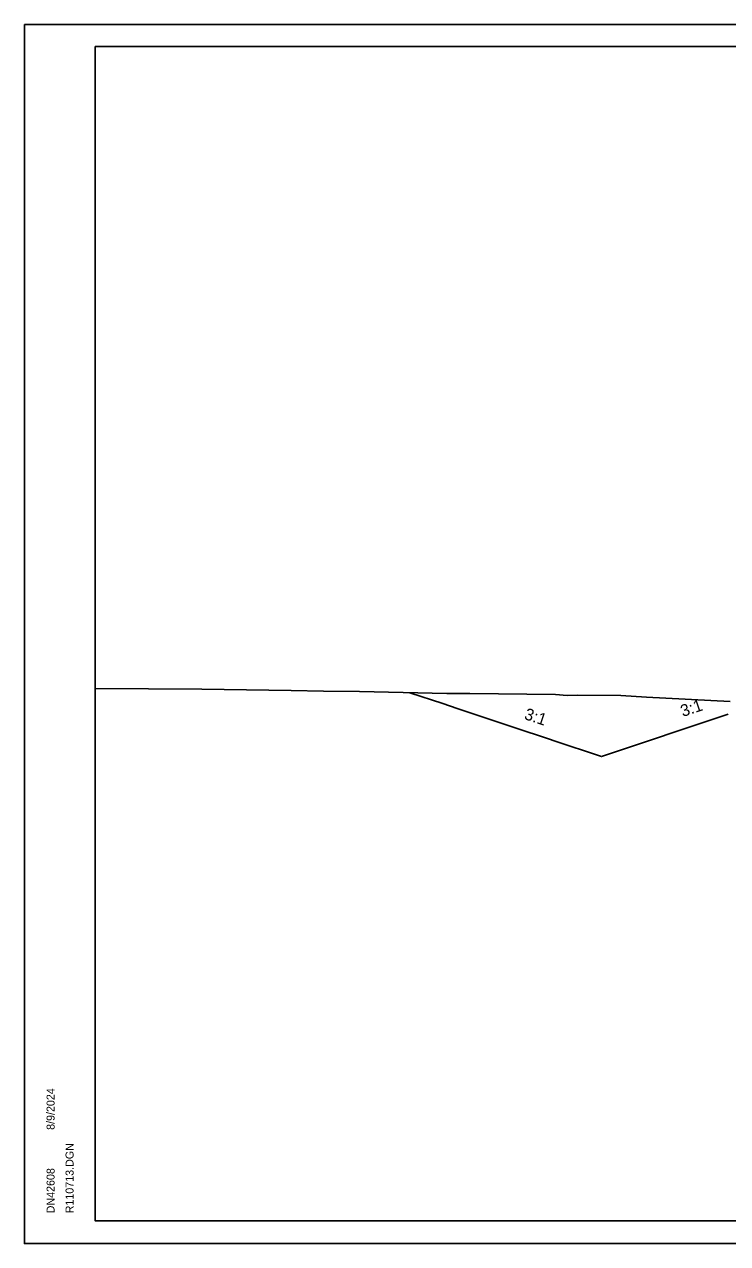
# Model space of a CAD drawing. Extents: x 1678017 to 1687792, y 404433 to 413488.
# Drawn here: x 1679716 to 1680331, y 406203 to 407270 of the extents above; entities that cross this region are included whole.
import ezdxf

# ---------------------------------------------------------------- set-up
doc = ezdxf.new("R2010")
doc.units = 0
for name, color, linetype in [('S_BUILDING', 7, 'Continuous'), ('S_ELECTRIC_UTILITIES', 7, 'Continuous'), ('S_MISC_STRUCTURES_ANNOT', 7, 'Continuous'), ('S_SECONDARY_CTL', 7, 'Continuous'), ('S_STREAM', 7, 'Continuous')]:
    doc.layers.add(name, color=color, linetype=linetype)

msp = doc.modelspace()

# ---------------------------------------------------------------- linework, layer by layer
at = {"layer": 'S_BUILDING'}
for p, q in [((1679778, 407250.2), (1681358.9, 407250.2)), ((1679778, 406222.9), (1679778, 407250.2)), ((1679778, 406222.9), (1679778, 406222.9)), ((1681358.9, 406222.9), (1679778, 406222.9))]:
    msp.add_line(p, q, dxfattribs=at)
at = {"layer": 'S_ELECTRIC_UTILITIES'}
msp.add_lwpolyline([(1680053.1, 406684.9), (1680081.9, 406675.4), (1680094.4, 406671.2), (1680129.5, 406659.5), (1680136.4, 406657.2), (1680139.9, 406656), (1680143.5, 406654.8), (1680176, 406644), (1680178.4, 406643.2), (1680220.6, 406629.1), (1680331.3, 406666.3)], dxfattribs=at)
at = {"layer": 'S_SECONDARY_CTL'}
msp.add_lwpolyline([(1679778, 406688.8), (1679871.1, 406688), (1679949.3, 406686.8), (1679977.5, 406686.3), (1680008.9, 406685.9), (1680085.4, 406684.2), (1680105.5, 406684.2), (1680180.4, 406683.3), (1680190.6, 406682.4), (1680199.6, 406682.9), (1680237.7, 406682.5), (1680260.1, 406681), (1680333.2, 406677.3)], dxfattribs=at)
at = {"layer": 'S_STREAM'}
for p, q in [((1679716, 407269.7), (1681382.7, 407269.7)), ((1679716, 406203), (1681382.7, 406203))]:
    msp.add_line(p, q, dxfattribs=at)
for points in [[(1679716, 407269.7), (1681382.7, 407269.7), (1681382.7, 406203), (1679716, 406203)], [(1680947.6, 407250.2), (1681045.7, 407250.2), (1681045.7, 407200.8), (1681126.3, 407200.8), (1681242.3, 407200.8), (1681242.3, 407037.5), (1681358.3, 407037.5), (1681358.9, 406222.9), (1679778, 406222.9), (1679778, 407250.2)]]:
    msp.add_lwpolyline(points, close=True, dxfattribs=at)

# ---------------------------------------------------------------- texts
at = {"layer": 'S_BUILDING'}
for s, p in [('8/9/2024', (1679742.4, 406302.5)), ('R110713.DGN', (1679759, 406229.5)), ('DN42608', (1679742.4, 406229.5))]:
    msp.add_text(s, height=7, rotation=90, dxfattribs=at).set_placement(p)
at = {"layer": 'S_MISC_STRUCTURES_ANNOT'}
for rotation, p in [(18.4497, (1680291.8, 406663.7)), (341.5651, (1680152.4, 406662.1))]:
    msp.add_text('3:1', height=10.36, rotation=rotation, dxfattribs=at).set_placement(p)

doc.saveas('drawing.dxf')
